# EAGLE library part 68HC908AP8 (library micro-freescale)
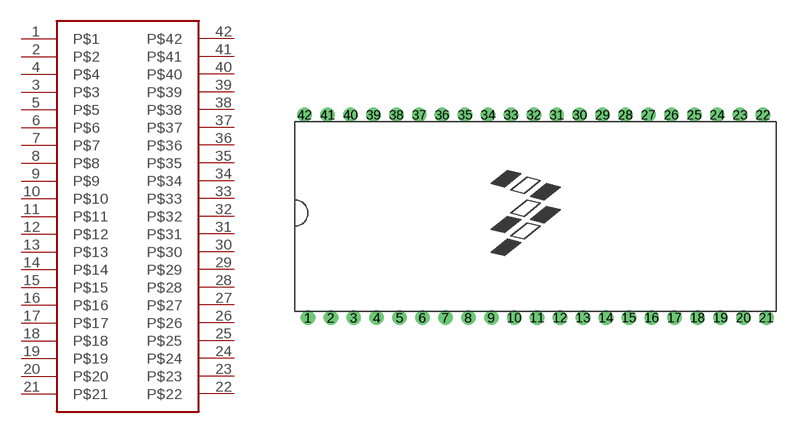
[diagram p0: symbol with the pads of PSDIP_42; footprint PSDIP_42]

Designator prefix -

## 68HC908AP8  [PSDIP_42]
1  P$1
2  P$2
3  P$3
4  P$4
5  P$5
6  P$6
7  P$7
8  P$8
9  P$9
10  P$10
11  P$11
12  P$12
13  P$13
14  P$14
15  P$15
16  P$16
17  P$17
18  P$18
19  P$19
20  P$20
21  P$21
22  P$22
23  P$23
24  P$24
25  P$25
26  P$26
27  P$27
28  P$28
29  P$29
30  P$30
31  P$31
32  P$32
33  P$33
34  P$34
35  P$35
36  P$36
37  P$37
38  P$38
39  P$39
40  P$40
41  P$41
42  P$42

## Footprint PSDIP_42 (pad centres in mm)
drill 0.61 pad 1.016 round: 1 -17.018,-8.636; 2 -15.24,-8.636; 3 -13.462,-8.636; 4 -11.684,-8.636; 5 -9.906,-8.636; 6 -8.128,-8.636; 7 -6.35,-8.636; 8 -4.572,-8.636; 9 -2.794,-8.636; 10 -1.016,-8.636; 11 0.762,-8.636; 12 2.54,-8.636; 13 4.318,-8.636; 14 6.096,-8.636; 15 7.874,-8.636; 16 9.652,-8.636; 17 11.43,-8.636; 18 13.208,-8.636; 19 14.986,-8.636; 20 16.764,-8.636; 21 18.542,-8.636; 22 18.288,7.112; 23 16.51,7.112; 24 14.732,7.112; 25 12.954,7.112; 26 11.176,7.112; 27 9.398,7.112; 28 7.62,7.112; 29 5.842,7.112; 30 4.064,7.112; 31 2.286,7.112; 32 0.508,7.112; 33 -1.27,7.112; 34 -3.048,7.112; 35 -4.826,7.112; 36 -6.604,7.112; 37 -8.382,7.112; 38 -10.16,7.112; 39 -11.938,7.112; 40 -13.716,7.112; 41 -15.494,7.112; 42 -17.272,7.112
